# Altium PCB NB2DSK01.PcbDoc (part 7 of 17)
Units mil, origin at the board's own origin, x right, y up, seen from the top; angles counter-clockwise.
Board outline 11815 x 6500.03 mil, 8 copper layers (Top Layer, MidLayer1, MidLayer2, GND, PWR, MidLayer3, MidLayer4, Bottom Layer), stack 74.62 mil thick; 798 components, 1002 nets, 3927 pads, 3182 vias.
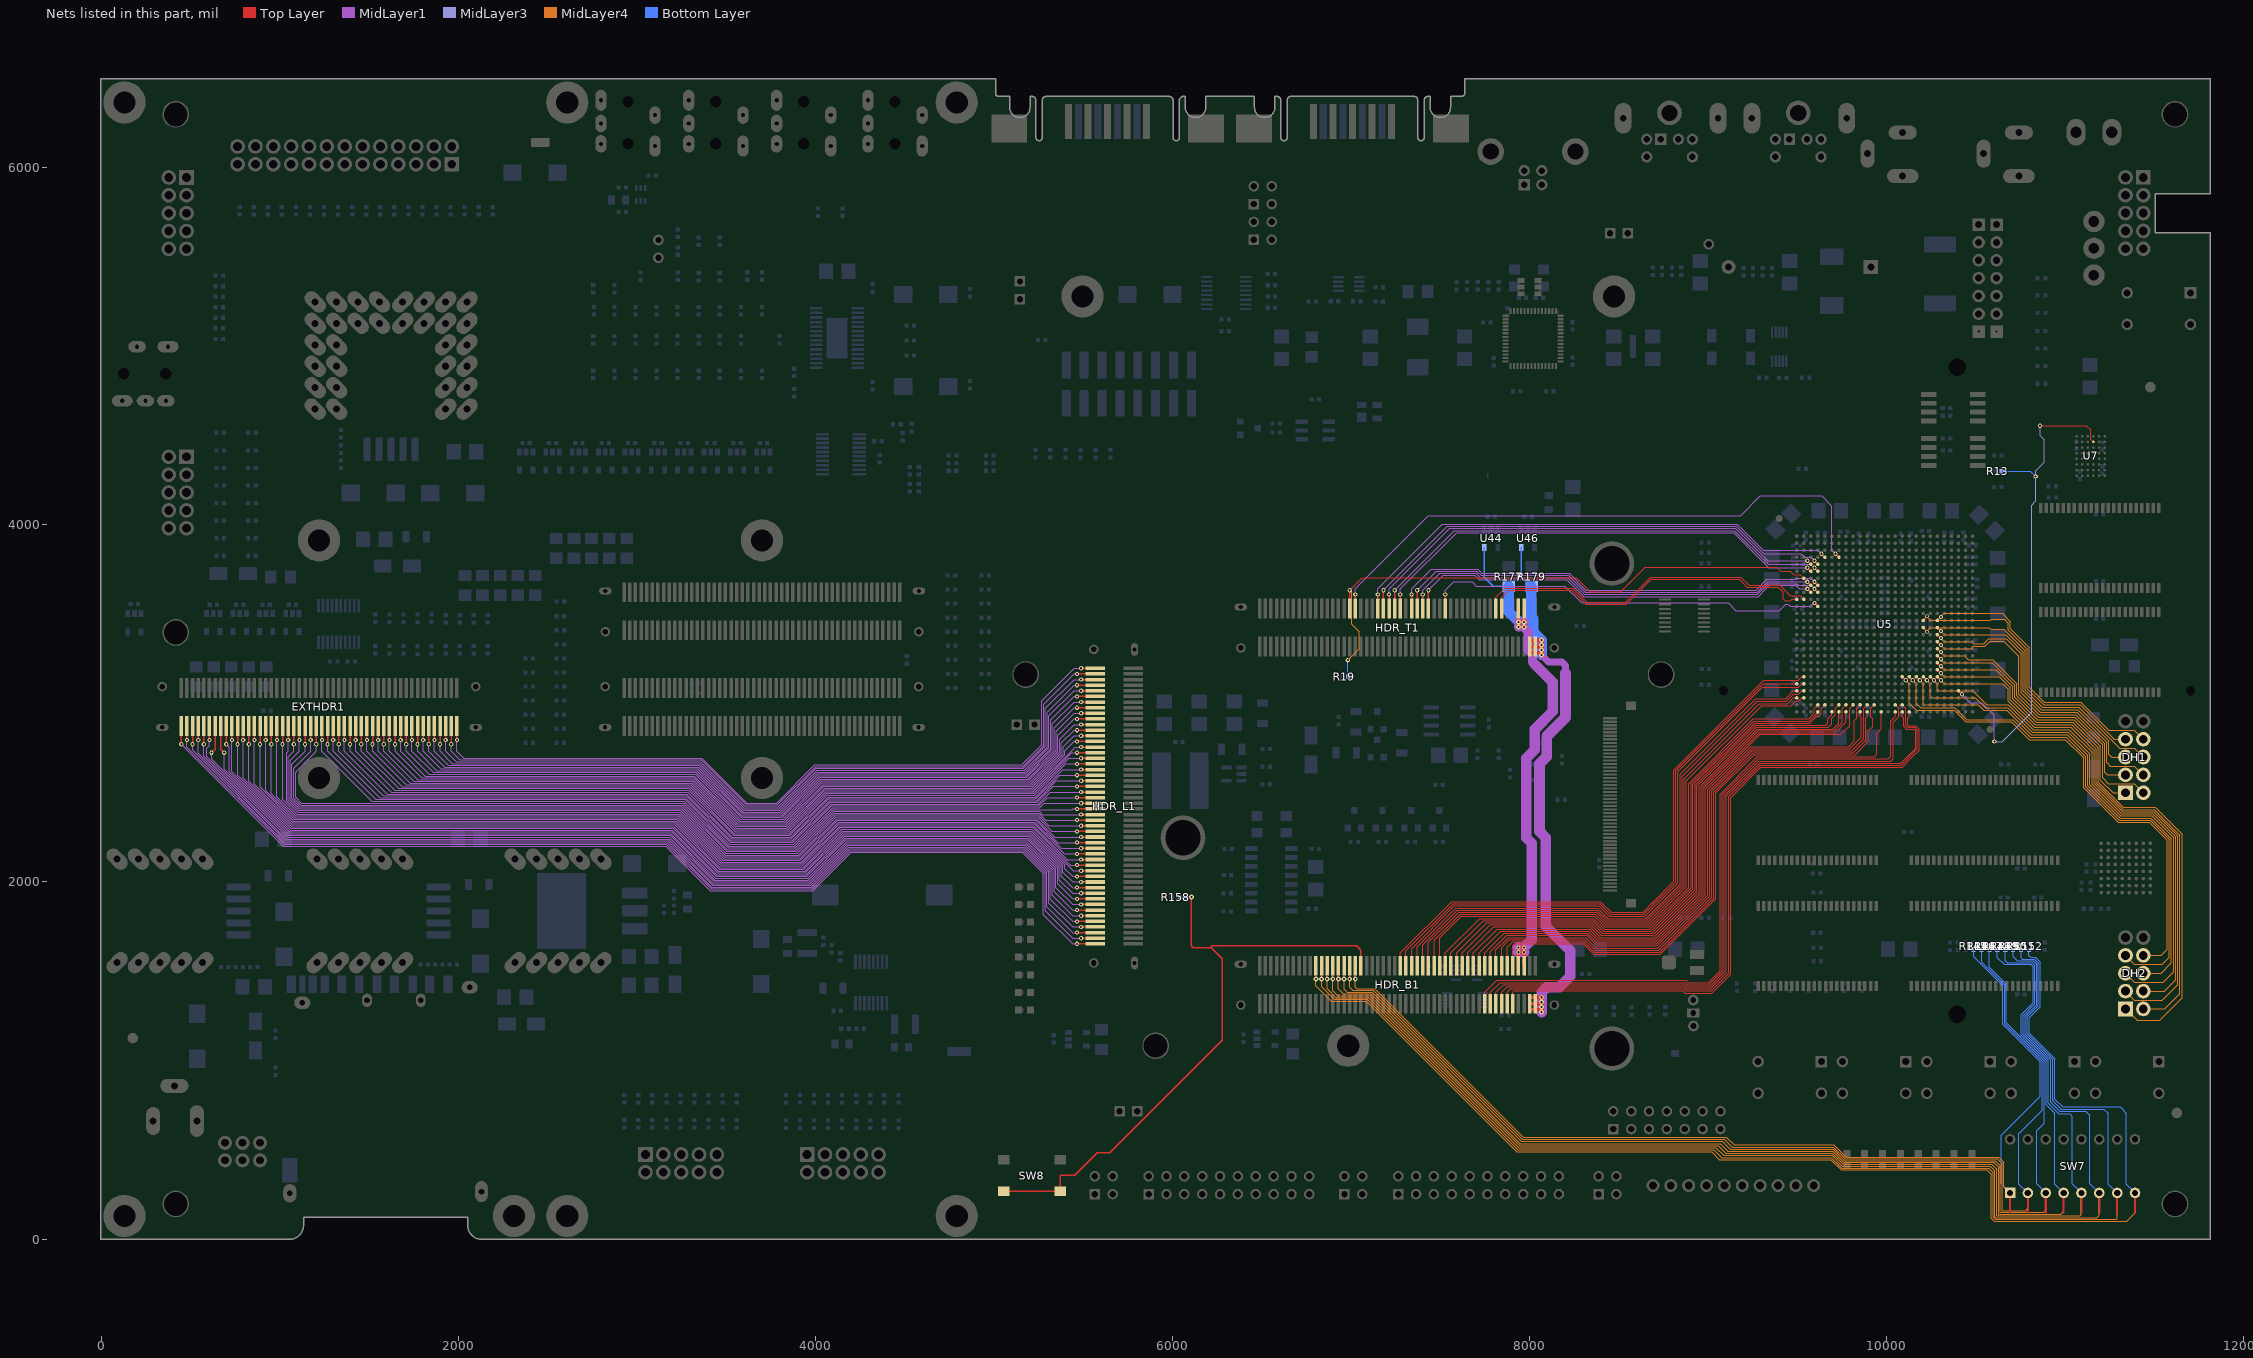
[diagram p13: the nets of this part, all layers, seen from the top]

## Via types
v1: diameter 23.62, hole 11.81, Top Layer to Bottom Layer, tented both sides, 1950 vias
v2: diameter 27.56, hole 11.81, Top Layer to Bottom Layer, tented both sides, 679 vias
v3: diameter 23.62, hole 11.81, Top Layer to Bottom Layer, 194 vias
v4: diameter 31.5, hole 11.81, Top Layer to Bottom Layer, tented both sides, 178 vias
v5: diameter 21.65, hole 11.81, Top Layer to Bottom Layer, tented both sides, 67 vias
v6: diameter 23.62, hole 11.81, Top Layer to Bottom Layer, tented bottom, 53 vias
v7: diameter 26, hole 11.81, Top Layer to Bottom Layer, tented both sides, 21 vias
v8: diameter 26, hole 11.81, Top Layer to Bottom Layer, 13 vias
v9: diameter 28, hole 11.81, Top Layer to Bottom Layer, 8 vias
v10: diameter 25.59, hole 11.81, Top Layer to Bottom Layer, tented both sides, 7 vias
v11: diameter 39.37, hole 11.81, Top Layer to Bottom Layer, tented both sides, 5 vias
v12: diameter 30, hole 11.81, Top Layer to Bottom Layer, 3 vias
v13: diameter 30, hole 11.81, Top Layer to Bottom Layer, tented both sides, 2 vias
v14: diameter 23, hole 11.81, Top Layer to Bottom Layer, tented both sides, 1 vias
v15: diameter 26.56, hole 11.81, Top Layer to Bottom Layer, tented both sides, 1 vias

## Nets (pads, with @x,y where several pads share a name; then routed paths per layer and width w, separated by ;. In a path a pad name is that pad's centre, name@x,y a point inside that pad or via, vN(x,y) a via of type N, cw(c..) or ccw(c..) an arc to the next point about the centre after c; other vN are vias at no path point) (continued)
DAU_PROG.ID3: HDR_T1.36 U5.D7 | length 3320.7
  Top Layer w7.87: HDR_T1.36@7023.62,3531.5 v1(7023.62,3610.24) ; v1(9712.6,3838.58) U5.D7@9732.28,3818.9
  MidLayer1 w5: v1(7023.62,3610.24) 7023.62,3641.73 7433.07,4051.18 9181.1,4051.18 9291.92,4162 9635.28,4162 9692.91,4104.37 9692.91,3858.27 v1(9712.6,3838.58)
DAU_PROG.INIT: HDR_T1.68 U5.L4 | length 2310.6
  Top Layer w7.87: HDR_T1.68@7527.56,3531.5 v1(7527.56,3610.24) ; v1(9594.49,3562.99) U5.L4@9614.17,3543.31
  MidLayer1 w5: v1(7527.56,3610.24) 7527.56,3633.86 7574.8,3681.1 7677.17,3681.1 7700.79,3657.48 8196.85,3657.48 8291.34,3562.99 9111.5,3562.99 9154.04,3520.45 9398.41,3520.45 9433.07,3555.12 9448.82,3555.12 9460.63,3543.31 9574.8,3543.31 v1(9594.49,3562.99)
DAU_PROG.INSTALLED: HDR_T1.34 R19.1 U5.G2 | length 3322.5
  Top Layer w5: v1(6992.13,3633.86) 7062.99,3704.73 8259.84,3704.73 8338.58,3625.99 8510.21,3625.99 8646.24,3762.01 9384.19,3762.01 9406.05,3740.16 9413.39,3740.16 9433.07,3740.16 9460.63,3740.16 9480.31,3720.47 9515.75,3720.47 U5.G2@9535.43,3700.79
  Top Layer w7.87: HDR_T1.34@6992.13,3531.5 v1(6992.13,3633.86)
  MidLayer4 w5: v1(6981.8,3242.47) 7046,3306.67 7046,3402.6 7004,3444.6 7004,3621.99 v1(6992.13,3633.86)
  Bottom Layer w5: R19.1@6981.8,3149.6 v1(6981.8,3242.47)
DAU_PROG.M0: HDR_T1.60 U5.J4 | length 2448.6
  Top Layer w7.87: HDR_T1.60@7401.58,3531.5 v1(7401.58,3610.24) ; v1(9594.49,3641.73) U5.J4@9614.17,3622.05
  MidLayer1 w5: v1(7401.58,3610.24) 7401.58,3633.86 7496.06,3728.35 7700.79,3728.35 7724.41,3704.73 8212.6,3704.73 8307.09,3610.24 9275.59,3610.24 9336.46,3671.1 9494.31,3671.1 9504,3661.42 9574.8,3661.42 v1(9594.49,3641.73)
DAU_PROG.M1: HDR_T1.58 U5.H3 | length 2432.7
  Top Layer w7.87: HDR_T1.58@7370.08,3531.5 v1(7370.08,3633.86) ; v1(9555.12,3681.1) U5.H3@9574.8,3661.42
  MidLayer1 w5: v1(7370.08,3633.86) 7476.38,3740.16 7704.72,3740.16 7728.35,3716.54 8216.54,3716.54 8311.02,3622.05 9273.26,3622.05 9332.31,3681.1 9413.39,3681.1 9433.07,3681.1 v1(9555.12,3681.1)
DAU_PROG.M2: HDR_T1.56 U5.H4 | length 2524.4
  Top Layer w7.87: HDR_T1.56@7338.58,3531.5 v1(7338.58,3610.24) ; v1(9594.49,3681.1) U5.H4@9614.17,3661.42
  MidLayer1 w5: v1(7338.58,3610.24) 7338.58,3641.73 7448.82,3751.97 7708.66,3751.97 7732.28,3728.35 8220.47,3728.35 8314.96,3633.86 9267.72,3633.86 9328.31,3694.45 9493.57,3694.45 9499.9,3700.79 9574.8,3700.79 v1(9594.49,3681.1)
DAU_PROG.PROG_CLK: HDR_T1.88 U5.K1 | length 1898.5
  Top Layer w5: HDR_T1.88@7842.52,3531.5 7842.52,3594.49 7881.89,3633.86 8236.22,3633.86 8279.53,3590.55 8314.96,3555.12 8541.35,3555.12 8681.39,3695.16 9174.92,3695.16 9219.29,3650.79 9393.63,3650.79 9421.21,3623.2 9421.21,3585.79 9432.2,3574.8 9460.63,3574.8 9468.5,3582.68 U5.K1@9496.06,3582.68
DAU_PROG.PROG_PWR_ON: HDR_T1.86 U5.K2 | length 1950.3
  Top Layer w5: HDR_T1.86@7811.02,3531.5 7811.02,3594.49 7862.21,3645.67 8240.16,3645.67 8318.9,3566.93 8538.16,3566.93 8677.68,3706.45 9183.31,3706.45 9228.98,3660.79 9402.2,3660.79 9419.54,3643.45 9460.63,3602.36 9515.75,3602.36 U5.K2@9535.43,3582.68
DAU_PROG.PROGRAM: HDR_T1.62 U5.J3 | length 2369.4
  Top Layer w7.87: HDR_T1.62@7433.07,3531.5 v1(7433.07,3633.86) ; v1(9555.12,3641.73) U5.J3@9574.8,3622.05
  MidLayer1 w5: v1(7433.07,3633.86) 7515.75,3716.54 7692.91,3716.54 7716.54,3692.91 8208.66,3692.91 8303.15,3598.43 9279.53,3598.43 9322.83,3641.73 9342.2,3661.1 9490.17,3661.1 9509.54,3641.73 v1(9555.12,3641.73)
DAU_RESET_SW: HDR_B1.38 R158.2 SW8.1 SW8.2 | length 3571.4
  Top Layer w7.87: SW8.2@5055.12,267.72 SW8.1@5370.47,267.72 5370.47,358.27 5452.76,358.27 5577.94,483.45 5648.68,483.45 6278.68,1113.45 6278.68,1570.02 6217.27,1631.43 ; v2(6105.79,1915) 6105.79,1642.21 6116.57,1631.43 6217.27,1631.43 ; HDR_B1.38@7055.12,1531.5 7055.12,1618.11 7031.5,1641.73 6217.27,1641.73 6217.27,1631.43
  Bottom Layer w15.75: R158.2@6038,1915 v2(6105.79,1915)
DAU_SPI.CLK: HDR_T1.46 U5.E4 | length 2771.9
  Top Layer w7.87: HDR_T1.46@7181.1,3531.5 v1(7181.1,3633.86) ; v1(9594.49,3799.21) U5.E4@9614.17,3779.53
  MidLayer1 w5: v1(7181.1,3633.86) 7539.37,3992.13 9156.64,3992.13 9280.31,3868.45 9310.18,3838.58 9413.39,3838.58 9433.07,3838.58 9519.69,3838.58 9539.37,3818.9 9574.8,3818.9 v1(9594.49,3799.21)
DAU_SPI.DIN: HDR_T1.50 U5.F4 | length 2705.6
  Top Layer w7.87: HDR_T1.50@7244.09,3531.5 v1(7244.1,3633.86) ; v1(9594.49,3759.84) U5.F4@9614.17,3740.16
  MidLayer1 w5: v1(7244.1,3633.86) 7578.74,3968.5 9146.86,3968.5 9335.83,3779.53 9413.39,3779.53 9433.07,3779.53 9574.8,3779.53 v1(9594.49,3759.84)
DAU_SPI.DOUT: HDR_T1.44 U5.D5 | length 2840.9
  Top Layer w7.87: HDR_T1.44@7149.61,3531.5 v1(7149.61,3610.24) ; v1(9633.86,3838.58) U5.D5@9653.54,3818.9
  MidLayer1 w5: v1(7149.61,3610.24) 7149.61,3641.73 7511.81,4003.94 9161.53,4003.94 9307.2,3858.27 9614.17,3858.27 v1(9633.86,3838.58)
DAU_SPI.MODE: HDR_T1.52 U5.F3 | length 2629.6
  Top Layer w7.87: HDR_T1.52@7275.59,3531.5 v1(7275.59,3610.24) ; v1(9555.12,3759.84) U5.F3@9574.8,3740.16
  MidLayer1 w5: v1(7275.59,3610.24) 7275.59,3641.73 7590.55,3956.69 9141.73,3956.69 9338.58,3759.84 9413.39,3759.84 9433.07,3759.84 v1(9555.12,3759.84)
DAU_SPI.SEL: HDR_T1.48 U5.E3 | length 2695.9
  Top Layer w7.87: HDR_T1.48@7212.6,3531.5 v1(7212.6,3610.24) ; v1(9555.12,3799.21) U5.E3@9574.8,3779.53
  MidLayer1 w5: v1(7212.6,3610.24) 7212.6,3641.73 7551.18,3980.32 9151.75,3980.32 9332.85,3799.21 9409.45,3799.21 9433.07,3799.21 v1(9555.12,3799.21)
DAU_TFT.BLIGHT: HDR_B1.91 U5.AF17 | length 3757.4
  Top Layer w5: HDR_B1.91@7905.51,1318.9 7905.51,1381.89 7913.39,1389.76 8858.27,1389.76 8870.08,1377.95 9019.69,1377.95 9125.98,1484.25 9125.98,2472.44 9295.28,2641.73 10085.73,2641.73 10149.68,2705.68 10181.68,2737.68 10181.68,2855.32 10161,2876 10121.13,2876 10118.11,2879.02 10118.11,2917.32 10125.98,2925.2 U5.AF17@10125.98,2952.76
DAU_TFT.BLUE0: HDR_B1.62 U5.AD1 | length 3161
  Top Layer w5: HDR_B1.62@7433.07,1531.5 7433.07,1661.42 7602.36,1830.71 8372.22,1830.71 8431.28,1771.65 8659.28,1771.65 8866.14,1978.52 8866.14,2578.91 9286.68,2999.45 9444.34,2999.45 9476.38,3031.5 U5.AD1@9496.06,3031.5
DAU_TFT.BLUE1: HDR_B1.64 U5.AD2 | length 3171
  Top Layer w5: HDR_B1.64@7464.57,1531.5 7464.57,1673.23 7610.24,1818.9 8367.33,1818.9 8426.38,1759.84 8664.17,1759.84 8877.95,1973.63 8877.95,2565.72 9300.68,2988.45 9464.83,2988.45 9488.19,3011.81 9503.94,3011.81 9523.62,3031.5 U5.AD2@9535.43,3031.5
DAU_TFT.BLUE2: HDR_B1.66 U5.AE4 | length 3220.5
  Top Layer w5: HDR_B1.66@7496.06,1531.5 7496.06,1687.06 7616.09,1807.09 8362.44,1807.09 8421.49,1748.03 8669.06,1748.03 8889.76,1968.74 8889.76,2551.18 9251.97,2913.39 9507.87,2913.39 9562.99,2913.39 9594.49,2944.88 9594.49,2972.44 U5.AE4@9614.17,2992.13
DAU_TFT.BLUE3: HDR_B1.68 U5.AF4 | length 3109.8
  Top Layer w5: HDR_B1.68@7527.56,1531.5 7527.56,1602.36 7720.47,1795.28 8357.54,1795.28 8416.6,1736.22 8673.95,1736.22 8901.58,1963.84 8901.57,2547.24 9255.91,2901.58 9566.93,2901.58 9570.87,2905.51 9614.17,2948.82 U5.AF4@9614.17,2952.76
DAU_TFT.BLUE4: HDR_B1.70 U5.AE5 | length 3150.7
  Top Layer w5: HDR_B1.70@7559.06,1531.5 7559.06,1602.36 7740.16,1783.47 8352.65,1783.47 8411.71,1724.41 8678.84,1724.41 8913.39,1958.95 8913.39,2543.31 9259.84,2889.76 9569.26,2889.76 9608.63,2929.13 9622.05,2929.13 9633.86,2940.95 9633.86,2972.44 U5.AE5@9653.54,2992.13
DAU_TFT.CL1: HDR_B1.88 U5.AE11 | length 3207.8
  Top Layer w5: HDR_B1.88@7842.52,1531.5 7842.52,1633.86 7885.83,1677.17 8308.62,1677.17 8367.68,1618.11 8722.88,1618.11 9019.69,1914.92 9019.69,2507.87 9215.38,2703.57 9247.26,2735.45 9802.68,2735.45 9870.08,2802.85 9870.08,2877.95 9870.08,2889.76 9870.08,2972.44 U5.AE11@9889.76,2992.13
DAU_TFT.CL2: HDR_B1.90 U5.AF11 | length 3149.2
  Top Layer w5: HDR_B1.90@7874.02,1531.5 7874.02,1633.86 7905.51,1665.36 8303.73,1665.36 8362.78,1606.3 8727.77,1606.3 9031.5,1910.03 9031.5,2503.94 9252.01,2724.45 9811.68,2724.45 9881.89,2794.66 9881.89,2877.95 9881.89,2889.76 9881.89,2917.32 9889.76,2925.2 U5.AF11@9889.76,2952.76
DAU_TFT.CL3: HDR_B1.92 U5.AE12 | length 3201.3
  Top Layer w5: HDR_B1.92@7905.51,1531.5 7905.51,1641.73 7917.32,1653.54 8298.84,1653.54 8357.89,1594.49 8732.66,1594.49 9043.31,1905.14 9043.31,2500 9256.76,2713.45 9822.68,2713.45 9897.64,2788.41 9897.64,2846.46 9921.26,2870.08 9921.26,2889.76 9921.26,2913.39 9909.45,2925.2 9909.45,2972.44 U5.AE12@9929.13,2992.13
DAU_TFT.DISP_ON: HDR_B1.89 U5.AE16 | length 3819.8
  Top Layer w5: HDR_B1.89@7874.02,1318.9 7874.02,1381.89 7893.7,1401.58 8862.2,1401.58 8874.02,1389.76 9015.75,1389.76 9114.17,1488.19 9114.17,2476.38 9291.34,2653.54 10079.72,2653.54 10171.68,2745.51 10171.68,2851.18 10156.86,2866 10116.14,2866 10106.3,2875.84 10106.3,2972.44 U5.AE16@10086.61,2992.13
DAU_TFT.GREEN0: HDR_B1.72 U5.AF6 | length 3147.4
  Top Layer w5: HDR_B1.72@7590.55,1531.5 7590.55,1602.36 7759.84,1771.65 8347.76,1771.65 8406.81,1712.6 8683.74,1712.6 8925.2,1954.06 8925.2,2539.37 9263.78,2877.95 9657.48,2877.95 9669.29,2889.76 9669.29,2913.39 9692.91,2937.01 U5.AF6@9692.91,2952.76
DAU_TFT.GREEN1: HDR_B1.74 U5.AE7 | length 3188.3
  Top Layer w5: HDR_B1.74@7622.05,1531.5 7622.05,1602.36 7779.53,1759.84 8342.87,1759.84 8401.92,1700.79 8688.63,1700.79 8937.01,1949.17 8937.01,2535.43 9267.72,2866.14 9673.23,2866.14 9692.91,2885.83 9692.91,2897.64 9692.91,2917.32 9712.6,2937.01 9712.6,2972.44 U5.AE7@9732.28,2992.13
DAU_TFT.GREEN2: HDR_B1.76 U5.AF7 | length 3138.8
  Top Layer w5: HDR_B1.76@7653.54,1531.5 7653.54,1602.36 7799.21,1748.03 8337.98,1748.03 8397.03,1688.98 8693.52,1688.98 8948.82,1944.28 8948.82,2531.5 9262.78,2845.45 9273.46,2856.14 9698.66,2856.14 9732.28,2889.76 U5.AF7@9732.28,2952.76
DAU_TFT.GREEN3: HDR_B1.78 U5.AE8 | length 3173.9
  Top Layer w5: HDR_B1.78@7685.04,1531.5 7685.04,1602.36 7818.9,1736.22 8333.08,1736.22 8392.14,1677.17 8698.41,1677.17 8960.63,1939.38 8960.63,2527.56 9279.21,2846.14 9706.37,2846.14 9751.97,2891.74 9751.97,2972.44 U5.AE8@9771.65,2992.13
DAU_TFT.GREEN4: HDR_B1.80 U5.AF8 | length 3113.5
  Top Layer w5: HDR_B1.80@7716.54,1531.5 7716.53,1602.36 7838.58,1724.41 8328.19,1724.41 8387.25,1665.36 8703.31,1665.36 8972.44,1934.49 8972.44,2523.62 9268.27,2819.45 9284.96,2836.14 9713.37,2836.14 9771.65,2894.43 U5.AF8@9771.65,2952.76
DAU_TFT.GREEN5: HDR_B1.82 U5.AE9 | length 3161.8
  Top Layer w5: HDR_B1.82@7748.03,1531.5 7748.03,1602.36 7858.27,1712.6 8323.3,1712.6 8382.35,1653.54 8708.2,1653.54 8984.25,1929.6 8984.25,2519.69 9290.71,2826.14 9743.46,2826.14 9791.34,2874.02 9791.34,2889.76 9791.34,2972.44 U5.AE9@9811.02,2992.13
DAU_TFT.IRQ: HDR_B1.81 U5.AF13 | length 3647.3
  Top Layer w5: HDR_B1.81@7748.03,1318.9 7748.03,1381.89 7814.96,1448.82 8877.95,1448.82 8889.76,1437.01 9000,1437.01 9066.93,1503.94 9066.93,2492.13 9275.59,2700.79 9929.13,2700.79 9944.88,2716.54 9944.88,2834.22 9968.5,2857.84 9968.5,2870.08 9968.5,2889.76 U5.AF13@9968.5,2952.76
DAU_TFT.M: HDR_B1.87 U5.AF16 | length 3796.5
  Top Layer w5: HDR_B1.87@7842.52,1318.9 7842.52,1381.89 7874.02,1413.39 8866.14,1413.39 8877.95,1401.58 9011.81,1401.58 9102.36,1492.13 9102.36,2480.32 9287.4,2665.36 10077.39,2665.36 10161.68,2749.65 10161.68,2847.03 10152.72,2856 10110.13,2856 10094.49,2871.65 10094.49,2917.32 10086.61,2925.2 U5.AF16@10086.61,2952.76
DAU_TFT.MUX: HDR_B1.85 U5.AE15 | length 3741.8
  Top Layer w5: HDR_B1.85@7811.02,1318.9 7811.02,1381.89 7854.33,1425.2 8870.08,1425.2 8881.89,1413.39 9007.87,1413.39 9090.55,1496.06 9090.55,2484.25 9283.46,2677.17 10023.62,2677.17 10035.55,2689.09 10035.55,2893.82 10066.93,2925.2 10066.93,2972.44 U5.AE15@10047.24,2992.13
DAU_TFT.POL: HDR_B1.83 U5.AF15 | length 3701.5
  Top Layer w5: HDR_B1.83@7779.53,1318.9 7779.53,1381.89 7834.65,1437.01 8874.02,1437.01 8885.83,1425.2 9003.94,1425.2 9078.74,1500 9078.74,2488.19 9279.53,2688.98 10007.87,2688.98 10023.68,2704.78 10023.68,2901.64 10047.24,2925.2 U5.AF15@10047.24,2952.76
DAU_TFT.RED0: HDR_B1.52 U5.AA2 | length 3410.4
  Top Layer w5: HDR_B1.52@7275.59,1531.5 7275.59,1602.36 7562.99,1889.76 8396.68,1889.76 8455.74,1830.71 8634.81,1830.71 8701.27,1897.16 ; 8683.62,1879.51 8807.09,2002.98 8807.09,2625.98 9311.02,3129.92 9413.39,3129.92 9433.07,3129.92 9503.94,3129.92 9523.62,3149.61 U5.AA2@9535.43,3149.61
DAU_TFT.RED1: HDR_B1.54 U5.AB1 | length 3305.8
  Top Layer w5: HDR_B1.54@7307.09,1531.5 7307.09,1614.17 7570.87,1877.95 8391.79,1877.95 8450.85,1818.9 8639.71,1818.9 8818.9,1998.09 8818.9,2622.05 9307.09,3110.24 9413.39,3110.24 9433.07,3110.24 U5.AB1@9496.06,3110.24
DAU_TFT.RED2: HDR_B1.56 U5.AB2 | length 3346.1
  Top Layer w5: HDR_B1.56@7338.58,1531.5 7338.58,1625.98 7578.74,1866.14 8386.9,1866.14 8445.95,1807.09 8644.6,1807.09 8717.97,1880.46 ; 8700.32,1862.81 8830.71,1993.2 8830.71,2618.11 9303.15,3090.55 9413.39,3090.55 9433.07,3090.55 9503.94,3090.55 9523.62,3110.24 U5.AB2@9535.43,3110.24
DAU_TFT.RED3: HDR_B1.58 U5.AC1 | length 3235.6
  Top Layer w5: HDR_B1.58@7370.08,1531.5 7370.08,1637.8 7586.61,1854.33 8382.01,1854.33 8441.06,1795.28 8649.49,1795.28 8842.52,1988.31 8842.52,2604.29 9265.79,3027.56 9413.39,3027.56 9433.07,3027.56 9476.38,3070.87 U5.AC1@9496.06,3070.87
DAU_TFT.RED4: HDR_B1.60 U5.AC2 | length 3246.2
  Top Layer w5: HDR_B1.60@7401.58,1531.5 7401.57,1649.61 7594.49,1842.52 8377.11,1842.52 8436.17,1783.47 8654.38,1783.47 8854.33,1983.41 8854.33,2592.1 9273.68,3011.45 9436.65,3011.45 9476.38,3051.18 9503.94,3051.18 9523.62,3070.87 U5.AC2@9535.43,3070.87
DAU_TFT.STH: HDR_B1.86 U5.AF10 | length 3169
  Top Layer w5: HDR_B1.86@7811.02,1531.5 7811.02,1619.72 7880.28,1688.98 8313.51,1688.98 8372.57,1629.92 8717.98,1629.92 9007.87,1919.81 9007.87,2511.81 9242.52,2746.45 9792.68,2746.45 9858.27,2812.04 9858.27,2877.95 9858.27,2889.76 9858.27,2917.32 9850.39,2925.2 U5.AF10@9850.39,2952.76
DAU_TFT.STV: HDR_B1.84 U5.AE10 | length 3215.6
  Top Layer w5: HDR_B1.84@7779.53,1531.5 7779.53,1608.3 7872.02,1700.79 8318.41,1700.79 8377.46,1641.73 8713.09,1641.73 8996.06,1924.71 8996.06,2515.75 9238.77,2758.45 9786.68,2758.45 9818.9,2790.67 9818.9,2877.95 9818.9,2889.76 9818.9,2905.51 9830.71,2917.32 9830.71,2972.44 U5.AE10@9850.39,2992.13
DBPOWER.3V3: HDR_B1.94 HDR_B1.96 HDR_T1.94 HDR_T1.96 R177.2 U44.5 | length 3225.7
  Top Layer w19.68: HDR_B1.94@7937.01,1531.5 v1(7937.01,1606.3) v1(7937.01,1633.86) ; v2(7968.5,3429.13) v2(7968.5,3456.69) HDR_T1.96@7968.5,3531.5
  Top Layer w20: v1(7937.01,1606.3) v1(7968.5,1606.3) ; v1(7937.01,1633.86) v1(7968.5,1633.86) v1(7968.5,1606.3) ; HDR_T1.94@7937.01,3531.5 v2(7937.01,3456.69) ; HDR_B1.96@7968.5,1531.5 v1(7968.5,1606.3) ; v2(7968.5,3429.13) v2(7937.01,3429.13) v2(7937.01,3456.69) ; v2(7968.5,3456.69) v2(7937.01,3456.69)
  MidLayer1 w51.18: v2(7937.01,3429.13) 7940.95,3429.13 7952.76,3440.94 ; v2(7937.01,3456.69) 7950.79,3442.91 7952.76,3440.94 ; v2(7968.5,3456.69) 7954.73,3442.91 7952.76,3440.94 ; 8031.5,3216.54 8015.75,3232.28 8015.75,3275.59 7992.13,3299.21 7992.13,3401.58 7966.54,3427.17 7952.76,3440.94
  MidLayer1 w59.06: v1(7937.01,1606.3) 7940.94,1606.3 7952.76,1618.11 7954.72,1620.08 ; v1(7937.01,1633.86) 7940.94,1633.86 7952.76,1622.05 7954.72,1620.08 ; v1(7968.5,1606.3) 7954.72,1620.08 ; 8031.5,3216.54 8129.92,3118.11 8129.92,2956.69 8027.56,2854.33 8027.56,2740.16 7980.32,2692.91 7980.32,2248.03 8011.81,2216.54 8011.81,1677.17 v1(7968.5,1633.86) 7954.72,1620.08
  Bottom Layer w7.87: U44.5@7746.06,3874.38 7746.06,3706.69 7797.24,3655.51 R177.2@7883.86,3655.51
  Bottom Layer w59.06: R177.2@7883.86,3655.51 7883.86,3513.78 7938.98,3458.66 7952.76,3444.88
DBPOWER.5V0: HDR_B1.97 HDR_B1.99 HDR_T1.97 HDR_T1.99 R179.2 U46.5 | length 3643.3
  Top Layer w19.68: HDR_B1.97@8000,1283.46 8031.5,1283.46 v2@8066.93,1283.46 ; HDR_B1.97@8000,1318.9 HDR_B1.99@8031.5,1318.9 v2@8066.93,1318.9 ; HDR_T1.97@8000,3283.46 8031.5,3283.46 v2@8066.93,3283.46 ; HDR_T1.97@8000,3318.9 HDR_T1.99@8031.5,3318.9 v2@8066.93,3318.9
  Top Layer w20: HDR_B1.97@8000,1354.33 8031.5,1354.33 v2(8066.93,1354.33) ; HDR_T1.97@8000,3354.33 8031.5,3354.33 v2(8066.93,3354.33)
  Top Layer w29.53: v2(8066.93,1271.65) 8066.93,1283.46 v2(8066.93,1299.21) 8066.93,1318.9 v2(8066.93,1326.77) v2(8066.93,1354.33) ; v2(8066.93,3271.65) 8066.93,3283.46 v2(8066.93,3299.21) 8066.93,3318.9 v2(8066.93,3326.77) v2(8066.93,3354.33)
  MidLayer1 w39.37: v2(8066.93,3354.33) v2(8066.93,3326.77) v2(8066.93,3299.21) v2(8066.93,3271.65) 8106.3,3232.28 8181.1,3232.28 8200.79,3212.6 8200.79,3169.29
  MidLayer1 w59.06: v2(8066.93,1271.65) v2(8066.93,1299.21) v2(8066.93,1326.77) v2(8066.93,1354.33) 8066.93,1381.89 8094.49,1409.45 8165.35,1409.45 8228.35,1472.44 8228.35,1614.17 8090.55,1751.97 8090.55,2248.03 8055.12,2283.46 8055.12,2661.42 8094.49,2700.79 8094.49,2814.96 8200.79,2921.26 8200.79,3169.29
  Bottom Layer w7.87: U46.5@7952.76,3874.38 7952.76,3708.66 R179.2@8007.87,3653.54
  Bottom Layer w59.06: R179.2@8007.87,3657.48 8007.87,3655.51 8007.87,3653.54 8007.87,3485.98 8019.68,3474.17 8019.68,3401.57 v2(8066.93,3354.33) v2(8066.93,3326.77) v2(8066.93,3299.21) v2(8066.93,3271.65)
DEBA.D0: DH1.1 U5.V21 | length 1521.4
  Top Layer w7.87: U5.V21@10283.46,3267.72 v1(10303.15,3248.03)
  MidLayer4 w5: v1(10303.15,3248.03) 10322.84,3228.35 10543.31,3228.35 10562.99,3228.35 10590.55,3228.35 10716.54,3102.36 10716.54,3035.43 10842.52,2909.45 11047.24,2909.45 11196.85,2759.84 11196.85,2570.87 11267.72,2500 DH1.1@11337.01,2500
DEBA.D1: DH1.2 U5.U21 | length 1635.4
  Top Layer w7.87: U5.U21@10283.46,3307.09 v1(10303.15,3287.4)
  MidLayer4 w5: v1(10303.15,3287.4) 10322.84,3267.72 10433.07,3267.72 10456.69,3244.1 10543.31,3244.1 10562.99,3244.1 10594.49,3244.1 10728.35,3110.24 10728.35,3043.31 10848.29,2923.37 11053.01,2923.37 11208.66,2767.72 11208.66,2582.68 11240.16,2551.18 11385.83,2551.18 DH1.2@11437.01,2500
DEBA.D2: DH1.3 U5.T21 | length 1617.5
  Top Layer w7.87: U5.T21@10283.46,3346.46 v1(10303.15,3326.77)
  MidLayer4 w5: v1(10303.15,3326.77) 10322.84,3307.09 10472.44,3307.09 10484.25,3318.9 10550.13,3318.9 10580.68,3349.45 10655.68,3349.45 10739.76,3265.37 10739.76,3235.53 ; 10740.16,3235.53 10740.16,3051.18 10854.05,2937.29 11058.78,2937.29 11220.47,2775.59 11220.47,2614.17 11234.65,2600 DH1.3@11337.01,2600
DEBA.D3: DH1.4 U5.R21 | length 1698.1
  Top Layer w7.87: U5.R21@10283.46,3385.83 v1(10303.15,3366.14)
  MidLayer4 w5: v1(10303.15,3366.14) 10322.84,3346.46 10472.44,3346.46 10484.25,3334.65 10543.31,3334.65 10571.12,3362.45 10669.04,3362.45 10751.97,3279.53 10751.97,3059.06 10859.82,2951.21 11064.54,2951.21 11232.28,2783.47 11232.28,2669.29 11251.97,2649.61 11387.4,2649.61 DH1.4@11437.01,2600
DEBA.D4: DH1.5 U5.P21 | length 1526.9
  Top Layer w7.87: U5.P21@10283.46,3425.2 v1(10303.15,3405.51)
  MidLayer4 w5: v1(10303.15,3405.51) 10322.84,3385.83 10543.31,3385.83 10562.99,3385.83 10665.35,3385.83 10763.78,3287.4 10763.78,3066.93 10865.58,2965.13 11070.31,2965.13 11244.09,2791.34 11244.09,2716.54 11260.63,2700 DH1.5@11337.01,2700
DEBA.D5: DH1.6 U5.P19 | length 1678.1
  Top Layer w7.87: U5.P19@10204.72,3425.2 v5@10224.41,3405.51
  MidLayer4 w5: v5@10224.41,3405.51 10244.09,3425.2 10543.31,3425.2 10562.99,3425.2 10574.8,3425.2 10584.55,3415.45 10655.41,3415.45 10775.59,3295.28 10775.59,3074.8 10871.35,2979.05 11076.07,2979.05 11305.12,2750 11387.01,2750 DH1.6@11437.01,2700
  other v5: 10224.41,3401.58
DEBA.D6: DH1.7 U5.N19 | length 1582.6
  Top Layer w7.87: U5.N19@10204.72,3464.57 v5@10224.41,3484.25
  MidLayer4 w5: v5@10224.41,3484.25 10244.09,3464.57 10543.31,3464.57 10562.99,3464.57 10578.74,3464.57 10586.61,3472.44 10657.48,3472.44 10681.1,3448.82 10681.1,3409.45 10787.4,3303.15 10787.4,3082.68 10877.95,2992.13 11082.68,2992.13 11274.8,2800 DH1.7@11337.01,2800
  other v5: 10224.41,3488.19
DEBA.D7: DH1.8 U5.N21 | length 1613.6
  Top Layer w7.87: U5.N21@10283.46,3464.57 v1(10303.15,3484.25)
  MidLayer4 w5: v1(10303.15,3484.25) 10322.84,3503.94 10543.31,3503.94 10562.99,3503.94 10645.67,3503.94 10692.91,3456.69 10692.91,3417.32 10799.21,3311.02 10799.21,3090.55 10881.89,3007.87 11086.61,3007.87 11244.09,2850.39 11386.62,2850.39 DH1.8@11437.01,2800
DEBB.D0: DH2.1 U5.W21 | length 3233.7
  Top Layer w7.87: U5.W21@10283.46,3228.35 v1(10303.15,3208.66)
  MidLayer4 w5: v1(10303.15,3208.66) 10322.84,3188.98 10543.31,3188.98 10562.98,3188.98 10610.25,3188.97 10704.72,3094.49 10704.72,3027.56 10837.74,2894.54 11042.47,2894.54 11185.04,2751.97 11185.04,2557.87 11325.59,2417.32 11503.94,2417.32 11653.54,2267.72 11653.54,1350.39 11527.56,1224.41 11401.58,1224.41 DH2.1@11337.01,1288.98
DEBB.D1: DH2.2 U5.Y21 | length 3020.3
  Top Layer w7.87: U5.Y21@10283.46,3188.98 v1(10303.15,3169.29)
  MidLayer4 w5: v1(10303.15,3169.29) 10322.84,3149.61 10543.31,3149.61 10562.99,3149.61 10629.92,3149.61 10692.92,3086.61 10692.92,3019.68 10831.98,2880.62 11036.7,2880.62 11173.23,2744.1 11173.23,2555.54 11323.26,2405.51 11499.04,2405.51 11641.73,2262.83 11641.73,1374.02 11556.69,1288.98 DH2.2@11437.01,1288.98
DEBB.D2: DH2.3 U5.AA21 | length 3044.6
  Top Layer w7.87: U5.AA21@10283.46,3149.61 v1(10303.15,3129.92)
  MidLayer4 w5: v1(10303.15,3129.92) 10322.84,3110.23 10543.31,3110.24 10562.99,3110.24 10649.61,3110.24 10681.1,3078.74 10681.1,3011.81 10826.21,2866.7 11030.94,2866.7 11161.42,2736.22 11161.42,2553.21 11320.92,2393.7 11494.15,2393.7 11629.92,2257.93 11629.92,1425.2 11543.31,1338.58 11387.4,1338.58 DH2.3@11337.01,1388.98
DEBB.D3: DH2.4 U5.AA20 | length 2875.9
  Top Layer w7.87: U5.AA20@10244.09,3149.61 v1(10263.78,3129.92)
  MidLayer4 w5: v1(10263.78,3129.92) 10283.47,3110.23 10283.47,3078.74 10291.34,3070.87 10480.32,3070.87 10559.06,2992.13 10562.99,2992.13 10578.74,2992.13 10681.1,2992.13 10820.45,2852.78 11023.14,2852.78 11149.61,2726.32 11149.61,2548.32 11316.03,2381.89 11489.26,2381.89 11618.11,2253.04 11618.11,1452.76 11554.33,1388.98 DH2.4@11437.01,1388.98
DEBB.D4: DH2.5 U5.AA19 | length 2981.8
  Top Layer w7.87: U5.AA19@10204.72,3149.61 v1(10224.41,3129.92)
  MidLayer4 w5: v1(10224.41,3129.92) 10244.1,3110.23 10244.1,3043.31 10255.91,3031.5 10496.06,3031.5 10551.18,2976.38 10562.99,2976.38 10578.74,2976.38 10677.17,2976.38 10814.68,2838.86 11016.31,2838.86 11137.8,2717.38 11137.8,2543.42 11311.14,2370.08 11484.37,2370.08 11606.3,2248.15 11606.3,1496.06 11549.24,1439 11386.99,1439 DH2.5@11337.01,1488.98
DEBB.D5: DH2.6 U5.AA18 | length 2849.2
  Top Layer w7.87: U5.AA18@10165.35,3149.61 v1(10185.04,3129.92)
  MidLayer4 w5: v1(10185.04,3129.92) 10204.73,3110.23 10204.73,2996.06 10208.66,2992.13 10511.81,2992.13 10543.31,2960.63 10562.99,2960.63 10578.74,2960.63 10673.23,2960.63 10808.92,2824.94 11010.54,2824.94 11125.98,2709.5 11125.98,2538.53 11306.25,2358.27 11479.48,2358.27 11594.49,2243.26 11594.49,1547.24 11536.22,1488.98 DH2.6@11437.01,1488.98
DEBB.D6: DH2.7 U5.AA17 | length 2939.8
  Top Layer w7.87: U5.AA17@10125.98,3149.61 v1(10145.67,3129.92)
  MidLayer4 w5: v1(10145.67,3129.92) 10165.35,3110.24 10165.35,3000 10188.98,2976.38 10381.89,2976.38 10448.82,2909.45 10562.99,2909.45 10578.74,2909.45 10704.72,2909.45 10803.15,2811.02 11005.62,2811.02 11114.17,2702.47 11114.17,2533.64 11301.35,2346.46 11474.58,2346.46 11582.68,2238.36 11582.68,1578.74 11543.31,1539.37 11386.61,1539.37 DH2.7@11337.01,1588.98
DEBB.D7: DH2.8 U5.AA16 | length 2784.4
  Top Layer w7.87: U5.AA16@10086.61,3149.61 v1(10106.3,3129.92)
  MidLayer4 w5: v1(10106.3,3129.92) 10125.98,3110.24 10125.98,3000 10165.35,2960.63 10377.95,2960.63 10440.95,2897.64 10562.99,2897.64 10578.74,2897.64 10696.85,2897.64 10797.91,2796.58 11000.37,2796.58 11102.36,2694.59 11102.36,2528.75 11296.46,2334.65 11469.69,2334.65 11570.87,2233.47 11570.87,1622.05 11537.8,1588.98 DH2.8@11437.01,1588.98
DIPSW.D0: HDR_B1.22 R152.1 SW7.8 | length 7488.6
  Top Layer w5: v8(6803.15,1456.69) HDR_B1.22@6803.15,1531.5
  Top Layer w11.81: 11390.32,148.43 SW7.8@11390.32,258.43
  MidLayer4 w5: v8(6803.15,1456.69) 6803.15,1419.85 6890.16,1332.84 7084.49,1332.84 7929.13,488.19 9019.69,488.19 9062.99,444.88 9687.56,444.88 9744.44,388 10560.74,388 10586,362.74 10586,117 10603,100 11343,100 11390.32,147.32 SW7.8@11390.32,258.43
  Bottom Layer w5: R152.1@10796.32,1618.11 10796.32,1588 10806.32,1578 10830.28,1578 10859,1549.28 10859,1299.94 10799.21,1240.16 10799.21,1151.94 10940.94,1010.21 10940.94,783.46 10984.25,740.16 11307.09,740.16 11342.52,704.72 11342.52,306.22 SW7.8@11390.32,258.43
DIPSW.D1: HDR_B1.24 R151.1 SW7.7 | length 7330.1
  Top Layer w5: v8(6834.65,1456.69) HDR_B1.24@6834.65,1531.5
  Top Layer w11.81: 11290.32,148.43 SW7.7@11290.32,258.43
  MidLayer4 w5: v8(6834.65,1456.69) 6834.65,1413 6904.81,1342.84 7091.19,1342.84 7934.03,500 9031.5,500 9074.8,456.69 9689.89,456.69 9748.58,398 10570.43,398 10596,372.43 10596,121.14 10607.14,110 11285,110 11290.32,115.32 SW7.7@11290.32,258.43
  Bottom Layer w5: R151.1@10752.03,1618.11 10752.03,1574.97 10759,1568 10826.14,1568 10849,1545.14 10849,1305.69 10787.4,1244.09 10787.4,1149.61 10929.13,1007.87 10929.13,775.59 10976.38,728.35 11216.54,728.35 11240.16,704.72 11240.16,308.58 SW7.7@11290.32,258.43
DIPSW.D2: HDR_B1.26 R150.1 SW7.6 | length 7126
  Top Layer w5: v8(6866.14,1456.69) HDR_B1.26@6866.14,1531.5
  Top Layer w11.81: 11190.32,148.43 SW7.6@11190.32,258.43
  MidLayer4 w5: v8(6866.14,1456.69) 6866.14,1401.86 6915.16,1352.84 7097.89,1352.84 7938.92,511.81 9043.31,511.81 9086.61,468.5 9692.22,468.5 9751.28,409.45 10578.66,409.45 10606,382.11 10606,125.28 10611.28,120 11177,120 11190.32,133.32 SW7.6@11190.32,258.43
  Bottom Layer w5: R150.1@10707.73,1618.11 10707.73,1580.27 10730,1558 10820,1558 10839,1539 10839,1311.44 10775.59,1248.03 10775.59,1147.28 10917.32,1005.54 10917.32,767.72 10968.5,716.54 11114.17,716.54 11137.8,692.91 11137.8,310.95 SW7.6@11190.32,258.43
DIPSW.D3: HDR_B1.28 R149.1 SW7.5 | length 6951
  Top Layer w5: v8(6897.64,1456.69) HDR_B1.28@6897.64,1531.5
  Top Layer w11.81: 11090.32,148.43 SW7.5@11090.32,258.43
  MidLayer4 w5: v8(6897.64,1456.69) 6897.64,1391 6925.8,1362.84 7104.6,1362.84 7331.3,1136.13 7943.81,523.62 9055.12,523.62 9098.43,480.32 9694.55,480.32 9755.42,419.45 10588.35,419.45 10616,391.8 10616,130 11083,130 11090.32,137.32 SW7.5@11090.32,258.43
  Bottom Layer w5: R149.1@10663.44,1618.11 10663.44,1559 10674.44,1548 10815.86,1548 10829,1534.86 10829,1317.19 10763.78,1251.97 10763.78,1144.94 10905.51,1003.21 10905.51,759.84 10964.57,700.79 11023.62,700.79 11039.37,685.04 11039.37,309.37 SW7.5@11090.32,258.43
DIPSW.D4: HDR_B1.30 R148.1 SW7.4 | length 6742.5
  Top Layer w5: v8(6929.13,1456.69) HDR_B1.30@6929.13,1531.5
  Top Layer w11.81: 10990.32,148.43 SW7.4@10990.32,258.43
  MidLayer4 w5: v8(6929.13,1456.69) 6929.13,1400.87 6957.16,1372.84 7111.3,1372.84 7948.7,535.43 9066.93,535.43 9110.24,492.13 9696.89,492.13 9759.56,429.45 10598.03,429.45 10626,401.48 10626,140 10974,140 10990.32,156.32 SW7.4@10990.32,258.43
  Bottom Layer w5: R148.1@10619.15,1618.11 10619.15,1576.85 10658,1538 10807.3,1538 10819,1526.3 10819,1322.94 10751.97,1255.91 10751.97,1142.61 10893.7,1000.88 10893.7,751.97 10940.94,704.72 10940.94,307.8 SW7.4@10990.32,258.43
DIPSW.D5: HDR_B1.32 R147.1 SW7.3 | length 6469.3
  Top Layer w5: v8(6960.63,1456.69) HDR_B1.32@6960.63,1531.5
  Top Layer w11.81: 10890.32,148.43 SW7.3@10890.32,258.43
  MidLayer4 w5: v8(6960.63,1456.69) 6960.63,1400.21 6978,1382.84 7118,1382.84 7953.6,547.24 9078.74,547.24 9122.05,503.94 9699.22,503.94 9763.7,439.45 10607.72,439.45 10636,411.17 10636,150 10878,150 10890.32,162.32 SW7.3@10890.32,258.43
  Bottom Layer w5: R147.1@10574.86,1618.11 10574.86,1521.52 10669.61,1426.77 10669.61,1210.83 10881.89,998.55 10881.89,649.61 10838.58,606.3 10838.58,310.16 SW7.3@10890.32,258.43
DIPSW.D6: HDR_B1.34 R146.1 SW7.2 | length 6365.9
  Top Layer w5: v8(6992.13,1456.69) HDR_B1.34@6992.13,1531.5
  Top Layer w11.81: 10790.32,148.43 SW7.2@10790.32,258.43
  MidLayer4 w5: v8(6992.13,1456.69) 6992.13,1410.87 7010.16,1392.84 7124.71,1392.84 7958.49,559.06 9090.55,559.06 9133.86,515.75 9701.55,515.75 9767.85,449.45 10617.4,449.45 10646,420.85 10646,160 10778,160 10790.32,172.32 SW7.2@10790.32,258.43
  Bottom Layer w5: R146.1@10530.57,1618.11 10530.57,1551.67 10659.61,1422.63 10659.61,1206.69 10870.08,996.22 10870.08,720.47 10740.16,590.55 10740.16,308.58 SW7.2@10790.32,258.43
DIPSW.D7: HDR_B1.36 R145.1 SW7.1 | length 6078.7
  Top Layer w5: v8(7023.62,1456.69) HDR_B1.36@7023.62,1531.5
  Top Layer w11.81: 10690.32,148.43 SW7.1@10690.32,258.43
  MidLayer4 w5: v8(7023.62,1456.69) 7023.62,1411.36 7032.14,1402.84 7131.41,1402.84 7963.38,570.87 9102.36,570.87 9145.67,527.56 9703.88,527.56 9771.99,459.45 10627.09,459.45 10656,430.54 10656,292.74 SW7.1@10690.32,258.43
  Bottom Layer w5: R145.1@10486.28,1618.11 10486.28,1581.82 10649.61,1418.49 10649.61,1202.55 10858.27,993.89 10858.27,799.21 10641.73,582.68 10641.73,307.01 SW7.1@10690.32,258.43
DONE: R13.2 U5.AC24 U7.B4 | length 2891.8
  Top Layer w5: v1(10858.27,4555.12) 11118.11,4555.12 11141.73,4531.5 11141.73,4480.32 U7.B4@11157.48,4464.57
  Top Layer w7.87: U5.AC24@10401.58,3070.87 v1(10421.26,3051.18)
  MidLayer1 w5: v1(10421.26,3051.18) 10468.5,3003.94 10531.5,3003.94 10602.54,2932.89 v1(10602.54,2786.37)
  MidLayer3 w5: v1(10602.54,2786.37) 10646.24,2786.37 10811.02,2951.15 10811.02,4110.24 10834.65,4133.86 10834.65,4271 10834.65,4303.15 10881.89,4350.39 10881.89,4476.38 10858.27,4500 v1@10858.27,4551.18
  Bottom Layer w5: R13.2@10641.64,4300.43 10804.57,4300.43 v1(10834,4271)
EXT_A.D0: EXTHDR1.2 HDR_L1.1 | length 4295.4
  Top Layer w7.87: v1(1992.13,2795.28) EXTHDR1.2@1992.13,2874.02 ; v1(5488.19,3196.85) HDR_L1.1@5566.93,3196.85
  MidLayer1 w5: v1(1992.13,2795.28) 1992.13,2732.28 2030.79,2693.62 3364.14,2693.62 3616.5,2441.26 3782.48,2441.26 3997.05,2655.83 5155.83,2655.83 5267.64,2767.64 5267.64,3015.67 5448.82,3196.85 v1(5488.19,3196.85)
EXT_A.D1: EXTHDR1.4 HDR_L1.3 | length 4311.9
  Top Layer w7.87: v1(1960.63,2771.65) EXTHDR1.4@1960.63,2874.02 ; v1(5464.57,3165.36) HDR_L1.3@5566.93,3165.36
  MidLayer1 w5: v1(1960.63,2771.65) 1960.63,2732.28 2009.29,2683.62 3360,2683.62 3612.36,2431.26 3786.63,2431.26 4001.19,2645.83 5159.97,2645.83 5277.64,2763.5 5277.64,2994.17 5448.82,3165.35 v1(5464.57,3165.36)
EXT_A.D2: EXTHDR1.6 HDR_L1.5 | length 4328.5
  Top Layer w7.87: v1(1929.14,2795.28) EXTHDR1.6@1929.13,2874.02 ; v1(5488.19,3133.86) HDR_L1.5@5566.93,3133.86
  MidLayer1 w5: v1(1929.14,2795.28) 1929.14,2732.28 1987.8,2673.62 3355.85,2673.62 3608.22,2421.26 3790.77,2421.26 4005.34,2635.83 5164.11,2635.83 5287.64,2759.35 5287.64,2972.68 5448.82,3133.86 v1(5488.19,3133.86)
EXT_A.D3: EXTHDR1.8 HDR_L1.7 | length 4345.1
  Top Layer w7.87: v1(1897.64,2771.65) EXTHDR1.8@1897.64,2874.02 ; v1(5464.57,3102.36) HDR_L1.7@5566.93,3102.36
  MidLayer1 w5: v1(1897.64,2771.65) 1897.64,2732.28 1966.3,2663.62 3351.71,2663.62 3604.07,2411.26 3794.91,2411.26 4009.48,2625.83 5168.25,2625.83 5297.64,2755.21 5297.64,2951.18 5448.82,3102.36 v1(5464.57,3102.36)
EXT_A.D4: EXTHDR1.10 HDR_L1.9 | length 4361.6
  Top Layer w7.87: v1(1866.14,2795.28) EXTHDR1.10@1866.14,2874.02 ; v1(5488.19,3070.87) HDR_L1.9@5566.93,3070.87
  MidLayer1 w5: v1(1866.14,2795.28) 1866.14,2732.28 1944.81,2653.62 3347.57,2653.62 3599.93,2401.26 3799.05,2401.26 4013.62,2615.83 5172.4,2615.83 5307.64,2751.07 5307.64,2929.69 5448.82,3070.87 v1(5488.19,3070.87)
EXT_A.D5: EXTHDR1.12 HDR_L1.11 | length 4378.2
  Top Layer w7.87: v1(1834.65,2771.65) EXTHDR1.12@1834.65,2874.02 ; v1(5464.57,3039.37) HDR_L1.11@5566.93,3039.37
  MidLayer1 w5: v1(1834.65,2771.65) 1834.65,2732.28 1923.31,2643.62 3343.43,2643.62 3595.79,2391.26 3803.2,2391.26 4017.76,2605.83 5176.54,2605.83 5317.64,2746.93 5317.64,2908.19 5448.82,3039.37 v1(5464.57,3039.37)
EXT_A.D6: EXTHDR1.14 HDR_L1.13 | length 4394.8
  Top Layer w7.87: v1(1803.15,2795.28) EXTHDR1.14@1803.15,2874.02 ; v1(5488.19,3007.88) HDR_L1.13@5566.93,3007.88
  MidLayer1 w5: v1(1803.15,2795.28) 1803.15,2732.28 1901.81,2633.62 3339.29,2633.62 3591.65,2381.26 3807.34,2381.26 4021.9,2595.83 5180.68,2595.83 5327.64,2742.79 5327.64,2886.7 5448.82,3007.88 v1(5488.19,3007.88)
EXT_A.D7: EXTHDR1.16 HDR_L1.15 | length 4411.3
  Top Layer w7.87: v1(1771.66,2771.65) EXTHDR1.16@1771.65,2874.02 ; v1(5464.57,2976.38) HDR_L1.15@5566.93,2976.38
  MidLayer1 w5: v1(1771.66,2771.65) 1771.66,2732.28 1880.32,2623.62 3335.14,2623.62 3587.51,2371.26 3811.48,2371.26 4026.05,2585.83 5184.82,2585.83 5337.64,2738.64 5337.64,2865.2 5448.82,2976.38 v1(5464.57,2976.38)
EXT_A.D8: EXTHDR1.18 HDR_L1.17 | length 4427.9
  Top Layer w7.87: v1(1740.16,2795.28) EXTHDR1.18@1740.16,2874.02 ; v1(5488.19,2944.88) HDR_L1.17@5566.93,2944.88
  MidLayer1 w5: v1(1740.16,2795.28) 1740.16,2732.28 1858.82,2613.62 3331,2613.62 3583.36,2361.26 3815.62,2361.26 4030.19,2575.83 5188.96,2575.83 5347.64,2734.5 5347.64,2843.7 5448.82,2944.88 v1(5488.19,2944.88)
EXT_A.D9: EXTHDR1.20 HDR_L1.19 | length 4444.5
  Top Layer w7.87: v1(1708.66,2771.65) EXTHDR1.20@1708.66,2874.02 ; v1(5464.57,2913.39) HDR_L1.19@5566.93,2913.39
  MidLayer1 w5: v1(1708.66,2771.65) 1708.66,2732.28 1837.32,2603.62 3326.86,2603.62 3579.22,2351.26 3819.76,2351.26 4034.33,2565.83 5193.11,2565.83 5357.64,2730.36 5357.64,2822.21 5448.82,2913.39 v1(5464.57,2913.39)
EXT_A.D10: EXTHDR1.22 HDR_L1.21 | length 4461
  Top Layer w7.87: v1(1677.17,2795.28) EXTHDR1.22@1677.17,2874.02 ; v1(5488.19,2881.89) HDR_L1.21@5566.93,2881.89
  MidLayer1 w5: v1(1677.17,2795.28) 1677.17,2732.28 1815.83,2593.62 3322.72,2593.62 3575.08,2341.26 3823.91,2341.26 4038.47,2555.83 5197.25,2555.83 5367.64,2726.22 5367.64,2800.71 5448.82,2881.89 v1(5488.19,2881.89)
EXT_A.D11: EXTHDR1.24 HDR_L1.23 | length 4477.6
  Top Layer w7.87: v1(1645.67,2771.65) EXTHDR1.24@1645.67,2874.02 ; v1(5464.57,2850.4) HDR_L1.23@5566.93,2850.39
  MidLayer1 w5: v1(1645.67,2771.65) 1645.67,2732.28 1794.33,2583.62 3318.57,2583.62 3570.94,2331.26 3828.05,2331.26 4042.62,2545.83 5201.39,2545.83 5377.64,2722.08 5377.64,2779.21 5448.82,2850.39 v1(5464.57,2850.4)
EXT_A.D12: EXTHDR1.26 HDR_L1.25 | length 4494.2
  Top Layer w7.87: v1(1614.18,2795.28) EXTHDR1.26@1614.17,2874.02 ; v1(5488.19,2818.9) HDR_L1.25@5566.93,2818.9
  MidLayer1 w5: v1(1614.18,2795.28) 1614.18,2732.28 1772.84,2573.62 3314.43,2573.62 3566.79,2321.26 3832.19,2321.26 4046.76,2535.83 5205.53,2535.83 5387.64,2717.93 5387.64,2757.72 5448.82,2818.9 v1(5488.19,2818.9)
EXT_A.D13: EXTHDR1.28 HDR_L1.27 | length 4510.7
  Top Layer w7.87: v1(1582.68,2771.65) EXTHDR1.28@1582.68,2874.02 ; v1(5464.57,2787.4) HDR_L1.27@5566.93,2787.4
  MidLayer1 w5: v1(1582.68,2771.65) 1582.68,2732.28 1751.34,2563.62 3310.29,2563.62 3562.65,2311.26 3836.33,2311.26 4050.9,2525.83 5209.67,2525.83 5397.64,2713.79 5397.64,2736.22 5448.82,2787.4 v1(5464.57,2787.4)
EXT_A.D14: EXTHDR1.30 HDR_L1.29 | length 4524.3
  Top Layer w7.87: v1(1551.18,2795.28) EXTHDR1.30@1551.18,2874.02 ; v1(5488.19,2755.91) HDR_L1.29@5566.93,2755.91
  MidLayer1 w5: v1(1551.18,2795.28) 1551.18,2732.28 1729.84,2553.62 3306.15,2553.62 3558.51,2301.26 3840.47,2301.26 4055.04,2515.83 5213.82,2515.83 5453.9,2755.91 v1(5488.19,2755.91)
EXT_A.D15: EXTHDR1.32 HDR_L1.31 | length 4551.1
  Top Layer w7.87: v1(1519.69,2771.65) EXTHDR1.32@1519.69,2874.02 ; v1(5464.57,2724.41) HDR_L1.31@5566.93,2724.41
  MidLayer1 w5: v1(1519.69,2771.65) 1519.69,2732.28 1708.35,2543.62 3302.01,2543.62 3554.37,2291.26 3844.62,2291.26 4059.18,2505.83 5217.96,2505.83 5436.54,2724.41 v1(5464.57,2724.41)
EXT_A.D16: EXTHDR1.34 HDR_L1.33 | length 4577.8
  Top Layer w7.87: v1(1488.19,2795.28) EXTHDR1.34@1488.19,2874.02 ; v1(5488.19,2692.91) HDR_L1.33@5566.93,2692.91
  MidLayer1 w5: v1(1488.19,2795.28) 1488.19,2732.28 1686.85,2533.62 3297.86,2533.62 3550.23,2281.26 3848.76,2281.26 4063.33,2495.83 5222.1,2495.83 5419.19,2692.91 v1(5488.19,2692.91)
EXT_A.D17: EXTHDR1.36 HDR_L1.35 | length 4604.5
  Top Layer w7.87: v1(1456.7,2771.65) EXTHDR1.36@1456.69,2874.02 ; v1(5464.57,2661.42) HDR_L1.35@5566.93,2661.42
  MidLayer1 w5: v1(1456.7,2771.65) 1456.7,2732.28 1665.36,2523.62 3293.72,2523.62 3546.08,2271.26 3852.9,2271.26 4067.47,2485.83 5226.24,2485.83 5401.84,2661.42 v1(5464.57,2661.42)
EXT_A.D18: EXTHDR1.38 HDR_L1.37 | length 4631.3
  Top Layer w7.87: v1(1425.2,2795.28) EXTHDR1.38@1425.2,2874.02 ; v1(5488.19,2629.92) HDR_L1.37@5566.93,2629.92
  MidLayer1 w5: v1(1425.2,2795.28) 1425.2,2732.28 1643.86,2513.62 3289.58,2513.62 3541.94,2261.26 3857.04,2261.26 4071.61,2475.83 5230.39,2475.83 5384.48,2629.92 v1(5488.19,2629.92)
EXT_A.D19: EXTHDR1.40 HDR_L1.39 | length 4658
  Top Layer w7.87: v1(1393.7,2771.65) EXTHDR1.40@1393.7,2874.02 ; v1(5464.57,2598.43) HDR_L1.39@5566.93,2598.43
  MidLayer1 w5: v1(1393.7,2771.65) 1393.7,2732.28 1623.23,2502.76 3283.77,2502.76 3535.26,2251.26 3861.19,2251.26 4075.75,2465.83 5234.53,2465.83 5367.13,2598.43 v1(5464.57,2598.43)
EXT_A.D20: EXTHDR1.42 HDR_L1.41 | length 4684.7
  Top Layer w7.87: v1(1362.21,2795.28) EXTHDR1.42@1362.2,2874.02 ; v1(5488.19,2566.93) HDR_L1.41@5566.93,2566.93
  MidLayer1 w5: v1(1362.21,2795.28) 1362.21,2732.28 1601.73,2492.76 3279.62,2492.76 3531.12,2241.26 3865.33,2241.26 4079.89,2455.83 5238.67,2455.83 5349.77,2566.93 v1(5488.19,2566.93)
EXT_A.D21: EXTHDR1.44 HDR_L1.43 | length 4711.5
  Top Layer w7.87: v1(1330.71,2771.65) EXTHDR1.44@1330.71,2874.02 ; v1(5464.57,2535.43) HDR_L1.43@5566.93,2535.43
  MidLayer1 w5: v1(1330.71,2771.65) 1330.71,2732.28 1580.24,2482.76 3275.48,2482.76 3526.98,2231.26 3869.47,2231.26 4084.04,2445.83 5242.81,2445.83 5332.42,2535.43 v1(5464.57,2535.43)
EXT_A.D22: EXTHDR1.46 HDR_L1.45 | length 4738.2
  Top Layer w7.87: v1(1299.21,2795.28) EXTHDR1.46@1299.21,2874.02 ; v1(5488.19,2503.94) HDR_L1.45@5566.93,2503.94
  MidLayer1 w5: v1(1299.21,2795.28) 1299.21,2732.28 1558.74,2472.76 3271.34,2472.76 3522.83,2221.26 3873.61,2221.26 4088.18,2435.83 5246.95,2435.83 5315.06,2503.94 v1(5488.19,2503.94)
EXT_A.D23: EXTHDR1.48 HDR_L1.47 | length 4764.9
  Top Layer w7.87: v1(1267.72,2771.65) EXTHDR1.48@1267.72,2874.02 ; v1(5464.57,2472.44) HDR_L1.47@5566.93,2472.44
  MidLayer1 w5: v1(1267.72,2771.65) 1267.72,2732.28 1537.24,2462.76 3267.2,2462.76 3518.69,2211.26 3877.75,2211.26 4092.32,2425.83 5251.1,2425.83 5297.71,2472.44 v1(5464.57,2472.44)
EXT_A.D24: EXTHDR1.50 HDR_L1.49 | length 4791.7
  Top Layer w7.87: v1(1236.22,2795.28) EXTHDR1.50@1236.22,2874.02 ; v1(5488.19,2440.95) HDR_L1.49@5566.93,2440.95
  MidLayer1 w5: v1(1236.22,2795.28) 1236.22,2732.28 1515.75,2452.76 3263.05,2452.76 3514.55,2201.26 3881.9,2201.26 4096.46,2415.83 5255.24,2415.83 5280.36,2440.95 v1(5488.19,2440.95)
EXT_A.D25: EXTHDR1.52 HDR_L1.51 | length 5134.6
  Top Layer w7.87: v1(1204.73,2771.65) EXTHDR1.52@1204.72,2874.02 ; v1(5464.57,2409.45) HDR_L1.51@5566.93,2409.45
  MidLayer1 w5: v1(1204.73,2771.65) 1204.73,2732.28 1088.43,2615.98 1088.43,2473.69 1121.32,2440.79 3260.88,2440.79 3510.72,2190.95 3886.17,2190.95 4100.74,2405.51 5437.01,2405.51 5440.95,2409.45 v1(5464.57,2409.45)
EXT_A.D26: EXTHDR1.54 HDR_L1.53 | length 5147.9
  Top Layer w7.87: v1(1173.23,2795.28) EXTHDR1.54@1173.23,2874.02 ; v1(5488.19,2377.95) HDR_L1.53@5566.93,2377.95
  MidLayer1 w5: v1(1173.23,2795.28) 1173.23,2732.28 1078.43,2637.48 1078.43,2469.54 1117.18,2430.79 3256.74,2430.79 3506.58,2180.95 3890.31,2180.95 4104.88,2395.51 5254.09,2395.51 5271.65,2377.95 v1(5488.19,2377.95)
EXT_A.D27: EXTHDR1.56 HDR_L1.55 | length 5164.5
  Top Layer w7.87: v1(1141.73,2771.65) EXTHDR1.56@1141.73,2874.02 ; v1(5464.57,2346.46) HDR_L1.55@5566.93,2346.46
  MidLayer1 w5: v1(1141.73,2771.65) 1141.73,2732.28 1068.43,2658.98 1068.43,2465.4 1113.04,2420.79 3252.6,2420.79 3502.44,2170.95 3894.45,2170.95 4109.02,2385.51 5249.95,2385.51 5289.01,2346.46 v1(5464.57,2346.46)
EXT_A.D28: EXTHDR1.58 HDR_L1.57 | length 5181.1
  Top Layer w7.87: v1(1110.24,2795.28) EXTHDR1.58@1110.24,2874.02 ; v1(5488.19,2314.96) HDR_L1.57@5566.93,2314.96
  MidLayer1 w5: v1(1110.24,2795.28) 1110.24,2732.28 1058.43,2680.47 1058.43,2461.26 1108.9,2410.79 3248.45,2410.79 3498.3,2160.95 3898.59,2160.95 4113.16,2375.51 5245.81,2375.51 5306.36,2314.96 v1(5488.19,2314.96)
EXT_A.D29: EXTHDR1.60 HDR_L1.59 | length 5197.6
  Top Layer w7.87: v1(1078.74,2771.65) EXTHDR1.60@1078.74,2874.02 ; v1(5464.57,2283.47) HDR_L1.59@5566.93,2283.47
  MidLayer1 w5: v1(1078.74,2771.65) 1078.74,2732.28 1048.43,2701.97 1048.43,2457.12 1104.76,2400.79 3244.31,2400.79 3494.15,2150.95 3902.74,2150.95 4117.3,2365.51 5241.67,2365.51 5323.72,2283.47 v1(5464.57,2283.47)
EXT_A.D30: EXTHDR1.62 HDR_L1.61 | length 5214.2
  Top Layer w7.09: v1(1047.25,2795.28) EXTHDR1.62@1047.24,2874.02 ; v1(5488.19,2251.97) HDR_L1.61@5566.93,2251.97
  MidLayer1 w5: v1(1047.25,2795.28) 1047.25,2732.28 1038.43,2723.46 1038.43,2452.98 1100.61,2390.79 3240.17,2390.79 3490.01,2140.95 3906.88,2140.95 4121.45,2355.51 5237.53,2355.51 5341.07,2251.97 v1(5488.19,2251.97)
EXT_A.D31: EXTHDR1.64 HDR_L1.63 | length 5241.3
  Top Layer w7.09: v1(1015.75,2771.65) EXTHDR1.64@1015.75,2874.02 ; v1(5464.57,2220.47) HDR_L1.63@5566.93,2220.47
  MidLayer1 w5: v1(1015.75,2771.65) 1015.75,2461.51 1096.47,2380.79 3236.03,2380.79 3485.87,2130.95 3911.02,2130.95 4125.59,2345.51 5233.38,2345.51 5358.42,2220.47 v1(5464.57,2220.47)
EXT_A.D32: EXTHDR1.66 HDR_L1.65 | length 5276.6
  Top Layer w7.09: v1(984.25,2795.28) EXTHDR1.66@984.25,2874.02 ; v1(5488.19,2188.98) HDR_L1.65@5566.93,2188.98
  MidLayer1 w5: v1(984.25,2795.28) 984.25,2477.26 1090.72,2370.79 3231.89,2370.79 3481.73,2120.95 3915.16,2120.95 4129.73,2335.51 5229.24,2335.51 5375.78,2188.98 v1(5488.19,2188.98)
EXT_A.D33: EXTHDR1.68 HDR_L1.67 | length 5311
  Top Layer w7.09: v1(952.76,2771.65) EXTHDR1.68@952.76,2874.02 ; v1(5464.57,2157.48) HDR_L1.67@5566.93,2157.48
  MidLayer1 w5: v1(952.76,2771.65) 952.76,2494.61 1086.58,2360.79 3227.74,2360.79 3477.59,2110.95 3919.31,2110.95 4133.87,2325.51 5225.1,2325.51 5393.13,2157.48 v1(5464.57,2157.48)
EXT_A.D34: EXTHDR1.70 HDR_L1.69 | length 5345.4
  Top Layer w7.09: v1(921.26,2795.28) EXTHDR1.70@921.26,2874.02 ; v1(5488.19,2125.99) HDR_L1.69@5566.93,2125.98
  MidLayer1 w5: v1(921.26,2795.28) 921.26,2511.97 1082.44,2350.79 3223.6,2350.79 3473.44,2100.95 3923.45,2100.95 4138.01,2315.51 5220.96,2315.51 5410.48,2125.99 v1(5488.19,2125.99)
EXT_A.D35: EXTHDR1.72 HDR_L1.71 | length 5379.7
  Top Layer w7.09: v1(889.77,2771.65) EXTHDR1.72@889.76,2874.02 ; v1(5464.57,2094.49) HDR_L1.71@5566.93,2094.49
  MidLayer1 w5: v1(889.77,2771.65) 889.76,2529.32 1078.3,2340.79 3219.46,2340.79 3469.3,2090.95 3927.59,2090.95 4142.16,2305.51 5216.82,2305.51 5427.84,2094.49 v1(5464.57,2094.49)
EXT_A.D36: EXTHDR1.74 HDR_L1.73 | length 5414.1
  Top Layer w7.09: v1(858.27,2795.28) EXTHDR1.74@858.27,2874.02 ; v1(5488.19,2062.99) HDR_L1.73@5566.93,2062.99
  MidLayer1 w5: v1(858.27,2795.28) 858.27,2546.67 1074.16,2330.79 3215.32,2330.79 3465.16,2080.95 3931.73,2080.95 4146.3,2295.51 5212.67,2295.51 5445.19,2062.99 v1(5488.19,2062.99)
EXT_A.D37: EXTHDR1.76 HDR_L1.75 | length 5461.6
  Top Layer w7.09: v1(826.77,2771.65) EXTHDR1.76@826.77,2874.02 ; v1(5464.57,2031.5) HDR_L1.75@5566.93,2031.5
  MidLayer1 w5: v1(826.77,2771.65) 826.77,2564.03 1070.01,2320.79 3211.18,2320.79 3461.02,2070.95 3935.87,2070.95 4150.44,2285.51 5208.53,2285.51 5396.49,2097.55 5396.49,2075.12 5440.12,2031.5 v1(5464.57,2031.5)
EXT_A.D38: EXTHDR1.78 HDR_L1.77 | length 5506.2
  Top Layer w7.09: v1(795.28,2795.28) EXTHDR1.78@795.28,2874.02 ; v1(5488.19,2000) HDR_L1.77@5566.93,2000
  MidLayer1 w5: v1(795.28,2795.28) 795.28,2581.38 1065.87,2310.79 3207.03,2310.79 3456.88,2060.95 3940.02,2060.95 4154.58,2275.51 5204.39,2275.51 5386.49,2093.41 5386.49,2053.62 5440.12,2000 v1(5488.19,2000)
EXT_A.D39: EXTHDR1.80 HDR_L1.79 | length 5550.7
  Top Layer w7.09: v1(763.78,2771.65) EXTHDR1.80@763.78,2874.02 ; v1(5464.57,1968.51) HDR_L1.79@5566.93,1968.5
  MidLayer1 w5: v1(763.78,2771.65) 763.78,2598.74 1061.73,2300.79 3202.89,2300.79 3452.73,2050.95 3944.16,2050.95 4158.73,2265.51 5200.25,2265.51 5376.49,2089.27 5376.49,2032.13 5440.12,1968.51 v1(5464.57,1968.51)
EXT_A.D40: EXTHDR1.82 HDR_L1.81 | length 5595.2
  Top Layer w7.09: v1(732.28,2795.28) EXTHDR1.82@732.28,2874.02 ; v1(5488.19,1937.01) HDR_L1.81@5566.93,1937.01
  MidLayer1 w5: v1(732.28,2795.28) 732.28,2616.09 1057.59,2290.79 3198.75,2290.79 3448.59,2040.95 3948.3,2040.95 4162.87,2255.51 5196.1,2255.51 5366.49,2085.12 5366.49,2010.63 5440.12,1937.01 v1(5488.19,1937.01)
EXT_A.D41: EXTHDR1.84 HDR_L1.83 | length 5639.8
  Top Layer w7.09: v1(700.79,2771.65) EXTHDR1.84@700.79,2874.02 ; v1(5464.57,1905.51) HDR_L1.83@5566.93,1905.51
  MidLayer1 w5: v1(700.79,2771.65) 716.54,2755.91 716.54,2617.7 1053.44,2280.79 3194.61,2280.79 3444.45,2030.95 3952.44,2030.95 4167.01,2245.51 5191.96,2245.51 5356.49,2080.98 5356.49,1989.13 5440.12,1905.51 v1(5464.57,1905.51)
EXT_A.D42: EXTHDR1.86 HDR_L1.85 | length 5684.3
  Top Layer w7.09: EXTHDR1.86@669.29,2874.02 669.29,2744.1 v1(688.98,2724.41) ; v1(5488.19,1874.02) HDR_L1.85@5566.93,1874.02
  MidLayer1 w5: v1(688.98,2724.41) 688.98,2631.11 1049.3,2270.79 3190.46,2270.79 3440.31,2020.95 3956.58,2020.95 4171.15,2235.51 5187.82,2235.51 5346.49,2076.84 5346.49,1967.64 5440.12,1874.02 v1(5488.19,1874.02)
EXT_A.D43: EXTHDR1.88 HDR_L1.87 | length 5734
  Top Layer w7.09: v1@625.98,2732.28 637.79,2744.09 EXTHDR1.88@637.79,2874.02 ; v1(5464.57,1842.52) HDR_L1.87@5566.93,1842.52
  MidLayer1 w5: v1(618.11,2724.41) 618.11,2687.84 1045.16,2260.79 3186.32,2260.79 3436.17,2010.95 3960.73,2010.95 4175.29,2225.51 5183.68,2225.51 5336.49,2072.7 5336.49,1946.14 5440.12,1842.52 v1(5464.57,1842.52)
EXT_A.D44: EXTHDR1.90 HDR_L1.89 | length 5786.5
  Top Layer w7.87: v1(606.3,2795.28) EXTHDR1.90@606.3,2874.02 ; v1(5488.19,1811.02) HDR_L1.89@5566.93,1811.02
  MidLayer1 w5: v1(606.3,2795.28) 606.3,2763.78 590.55,2748.03 590.55,2701.25 1041.02,2250.79 3182.18,2250.79 3432.02,2000.95 3964.87,2000.95 4179.44,2215.51 5179.54,2215.51 5326.49,2068.55 5326.49,1924.64 5440.12,1811.02 v1(5488.19,1811.02)
EXT_A.D45: EXTHDR1.92 HDR_L1.91 | length 5818
  Top Layer w7.87: v1(574.8,2771.65) EXTHDR1.92@574.8,2874.02 ; v1(5464.57,1779.53) HDR_L1.91@5566.93,1779.53
  MidLayer1 w5: v1(574.8,2771.65) 574.8,2702.86 1036.88,2240.79 3178.04,2240.79 3427.88,1990.95 3969.01,1990.95 4183.58,2205.51 5175.39,2205.51 5316.49,2064.41 5316.49,1903.15 5440.12,1779.53 v1(5464.57,1779.53)
EXT_A.D46: EXTHDR1.94 HDR_L1.93 | length 5862.5
  Top Layer w7.87: v1(543.31,2795.28) EXTHDR1.94@543.31,2874.02 ; v1(5488.19,1748.03) HDR_L1.93@5566.93,1748.03
  MidLayer1 w5: v1(543.31,2795.28) 543.31,2720.22 1032.73,2230.79 3173.9,2230.79 3423.74,1980.95 3973.15,1980.95 4187.72,2195.51 5171.25,2195.51 5306.49,2060.27 5306.49,1881.65 5440.12,1748.03 v1(5488.19,1748.03)
EXT_A.D47: EXTHDR1.96 HDR_L1.95 | length 5907
  Top Layer w7.87: v1(511.81,2771.65) EXTHDR1.96@511.81,2874.02 ; v1(5464.57,1716.54) HDR_L1.95@5566.93,1716.54
  MidLayer1 w5: v1(511.81,2771.65) 511.81,2737.57 1028.59,2220.79 3169.75,2220.79 3419.6,1970.95 3977.3,1970.95 4191.86,2185.51 5167.11,2185.51 5296.49,2056.13 5296.49,1860.16 5440.12,1716.54 v1(5464.57,1716.54)
EXT_A.D48: EXTHDR1.98 HDR_L1.97 | length 5951.6
  Top Layer w7.87: v1(480.32,2795.28) EXTHDR1.98@480.31,2874.02 ; v1(5488.19,1685.04) HDR_L1.97@5566.93,1685.04
  MidLayer1 w5: v1(480.32,2795.28) 480.31,2754.92 1024.45,2210.79 3165.61,2210.79 3415.45,1960.95 3981.44,1960.95 4196,2175.51 5162.97,2175.51 5286.49,2051.99 5286.49,1838.66 5440.12,1685.04 v1(5488.19,1685.04)
EXT_A.D49: EXTHDR1.100 HDR_L1.99 | length 5997.4
  Top Layer w7.87: v1(448.82,2771.65) EXTHDR1.100@448.82,2874.02 ; v1(5464.57,1653.54) HDR_L1.99@5566.93,1653.54
  MidLayer1 w5: v1(448.82,2771.65) 448.82,2772.28 449.13,2771.97 1020.31,2200.79 3161.47,2200.79 3411.31,1950.95 3985.58,1950.95 4200.15,2165.51 5158.83,2165.51 5276.49,2047.84 5276.49,1817.17 5440.12,1653.54 v1(5464.57,1653.54)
